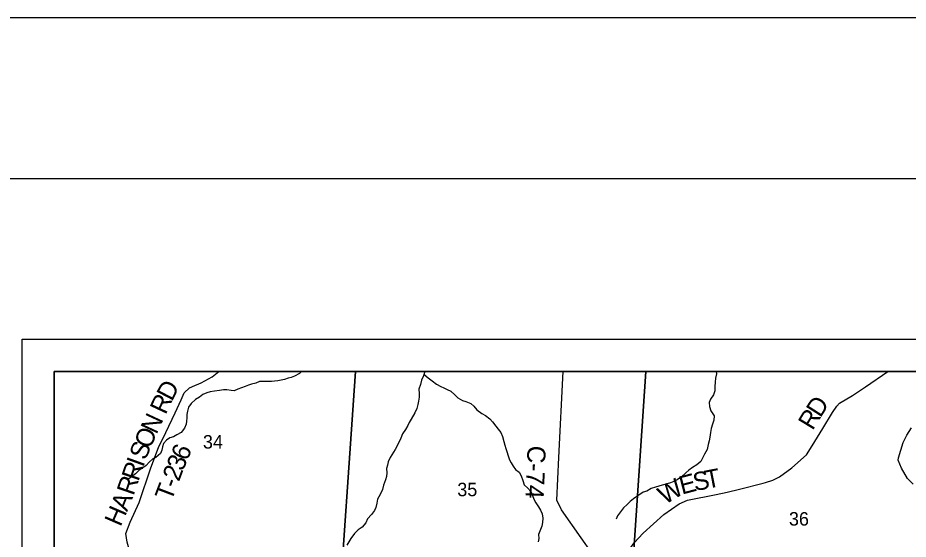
# Model space of a CAD drawing. Extents: x 0 to 34, y 0 to 22.
# Drawn here: x 23.403 to 26.174, y 20.378 to 22 of the extents above; entities that cross this region are included whole.
import ezdxf

# ---------------------------------------------------------------- set-up
doc = ezdxf.new("R2010")
doc.units = 0
for name, color, linetype in [('GM_X_City_Street', 7, 'Continuous'), ('GM_X_Corporation', 7, 'Continuous'), ('GM_X_County_Road', 7, 'Continuous'), ('GM_X_County_Road_Text', 7, 'Continuous'), ('GM_X_Minor_River', 7, 'Continuous'), ('GM_X_Section_Text', 7, 'Continuous'), ('GM_X_Township_Road', 7, 'Continuous'), ('GM_X_Township_Road_Text', 7, 'Continuous'), ('SH_Border', 7, 'Continuous'), ('SH_Cut_Line', 7, 'Continuous'), ('SH_Data', 7, 'Continuous')]:
    doc.layers.add(name, color=color, linetype=linetype)

msp = doc.modelspace()

# ---------------------------------------------------------------- linework, layer by layer
at = {"layer": 'GM_X_City_Street'}
msp.add_line((25.0865, 20.6324), (25.1003, 20.9), dxfattribs=at)
at = {"layer": 'GM_X_Corporation'}
for points in [[(24.4541, 20.9), (23.5167, 20.9), (23.5167, 20.1488), (24.2381, 20.0885), (24.3968, 20.0768)], [(26.3743, 20.9), (23.5167, 20.9), (23.5167, 20.1476), (23.8215, 20.1257), (24.2296, 20.084), (24.3889, 20.0736), (25.117, 20.0172), (25.2916, 20.0037), (25.482, 19.99), (25.7174, 19.9778), (26.3029, 19.931), (26.3351, 20.3683)], [(25.3573, 20.9), (24.4541, 20.9), (24.3968, 20.0768), (25.2979, 20.0049)], [(26.378, 20.9), (25.3573, 20.9), (25.2979, 20.0049), (26.302, 19.9328)]]:
    msp.add_lwpolyline(points, close=True, dxfattribs=at)
at = {"layer": 'GM_X_County_Road'}
for points in [[(25.2581, 20.2711), (25.3057, 20.3451), (25.3211, 20.367), (25.3495, 20.3964), (25.4138, 20.455), (25.4611, 20.4877), (25.4877, 20.4997), (25.5761, 20.5175), (25.6105, 20.5241), (25.6487, 20.5333), (25.723, 20.5524), (25.7304, 20.5544), (25.7524, 20.5617), (25.7731, 20.5722), (25.8117, 20.5997), (25.8576, 20.6409), (25.8752, 20.6681), (25.9079, 20.7222), (25.9386, 20.7725), (25.9523, 20.7916), (25.9606, 20.8013), (26.0006, 20.8252), (26.0414, 20.8523), (26.1102, 20.9)], [(25.2581, 20.2711), (25.2366, 20.286), (25.2278, 20.2932), (25.2057, 20.3136), (25.1884, 20.337), (25.1568, 20.3822), (25.0954, 20.4698), (25.0807, 20.4992), (25.0865, 20.6324)]]:
    msp.add_lwpolyline(points, dxfattribs=at)
at = {"layer": 'GM_X_Minor_River'}
for points in [[(24.2864, 20.9), (24.2801, 20.894), (24.2642, 20.885), (24.2539, 20.8809), (24.2441, 20.8794), (24.2334, 20.8749), (24.2225, 20.8727), (24.2126, 20.8709), (24.2024, 20.8702), (24.1925, 20.8691), (24.18, 20.8689), (24.1679, 20.8686), (24.1551, 20.869), (24.1441, 20.8638), (24.1304, 20.8601), (24.1209, 20.8575), (24.1103, 20.8534), (24.0997, 20.8485), (24.0883, 20.8444), (24.0766, 20.84), (24.0667, 20.8404), (24.0531, 20.8428), (24.0429, 20.8428), (24.0308, 20.8406), (24.0156, 20.8389), (24.0016, 20.8367), (23.9914, 20.8337), (23.9785, 20.8277), (23.9682, 20.8194), (23.956, 20.8123), (23.9423, 20.8007), (23.9343, 20.7886), (23.9312, 20.7765), (23.9292, 20.7662), (23.9292, 20.7552), (23.9283, 20.745), (23.9268, 20.7355), (23.9214, 20.7231), (23.9114, 20.7098), (23.8981, 20.7024), (23.8875, 20.6967), (23.8761, 20.693), (23.8662, 20.6859), (23.8567, 20.6753), (23.8536, 20.6651), (23.8513, 20.6553), (23.8467, 20.6451), (23.833, 20.6326), (23.8235, 20.6285), (23.8117, 20.6176), (23.8029, 20.6078), (23.7892, 20.5984), (23.7793, 20.5916), (23.769, 20.5819), (23.7572, 20.5717), (23.7443, 20.5623)], [(24.6695, 20.9), (24.6657, 20.8865), (24.6599, 20.8729), (24.6568, 20.8596), (24.651, 20.8452), (24.652, 20.8316), (24.6523, 20.8194), (24.65, 20.8077), (24.648, 20.7975), (24.6449, 20.7846), (24.6391, 20.771), (24.6276, 20.7513), (24.6215, 20.7415), (24.6169, 20.7313), (24.6093, 20.7189), (24.6008, 20.7056), (24.5947, 20.6928), (24.5878, 20.6773), (24.5774, 20.6569), (24.5621, 20.6327), (24.5556, 20.6191), (24.5536, 20.6081), (24.5509, 20.5979), (24.5516, 20.5842), (24.5508, 20.5729), (24.5477, 20.5626), (24.5415, 20.5464), (24.5376, 20.5331), (24.5303, 20.5169), (24.523, 20.5029), (24.5207, 20.49), (24.5172, 20.4767), (24.5133, 20.4669), (24.5038, 20.4552), (24.4916, 20.4417), (24.4862, 20.4288), (24.4748, 20.4152), (24.4626, 20.407), (24.4504, 20.3957), (24.4397, 20.3798), (24.4267, 20.3594)], [(25.5761, 20.9), (25.5776, 20.8926), (25.5749, 20.8786), (25.5733, 20.8669), (25.5728, 20.8528), (25.5727, 20.8396), (25.5681, 20.8271), (25.5585, 20.8135), (25.5551, 20.8036), (25.5561, 20.7904), (25.5602, 20.7774), (25.5699, 20.7618), (25.5691, 20.7486), (25.5648, 20.7357), (25.5609, 20.7225), (25.559, 20.7103), (25.557, 20.6956), (25.555, 20.6842), (25.5519, 20.6728), (25.548, 20.6569), (25.5403, 20.643), (25.5288, 20.6203), (25.5167, 20.609), (25.503, 20.6007), (25.4916, 20.5925), (25.4821, 20.5842), (25.4683, 20.5718), (25.4554, 20.5631), (25.4444, 20.5571), (25.4345, 20.553), (25.4243, 20.55), (25.408, 20.5464), (25.3981, 20.5434), (25.3879, 20.54), (25.3743, 20.536), (25.361, 20.5277), (25.3492, 20.5244), (25.3329, 20.5135), (25.3192, 20.5041), (25.3093, 20.4958), (25.299, 20.486), (25.2883, 20.4755), (25.2792, 20.4634), (25.2696, 20.4506), (25.265, 20.4403)], [(24.6672, 20.8919), (24.68, 20.8799), (24.6924, 20.8711), (24.7056, 20.86), (24.7192, 20.8528), (24.7293, 20.8493), (24.7391, 20.8439), (24.7512, 20.8381), (24.7633, 20.8274), (24.773, 20.8179), (24.7866, 20.8098), (24.7975, 20.8063), (24.8126, 20.8002), (24.8224, 20.7922), (24.8318, 20.7807), (24.8469, 20.7696), (24.8589, 20.7627), (24.8717, 20.7528), (24.88, 20.7429), (24.8905, 20.7295), (24.8976, 20.72), (24.9059, 20.7097), (24.9115, 20.6971), (24.9155, 20.6819), (24.9188, 20.6702), (24.9222, 20.6599), (24.9251, 20.6504), (24.9292, 20.6379), (24.9337, 20.6253), (24.9385, 20.6158), (24.9445, 20.6055), (24.9516, 20.5945), (24.9637, 20.5864), (24.97, 20.5754), (24.9745, 20.5606), (24.9789, 20.5473), (24.9906, 20.5366), (24.9992, 20.5267), (25.0052, 20.5141), (25.0089, 20.5031), (25.0149, 20.4913), (25.0231, 20.4783), (25.0298, 20.4681), (25.0351, 20.4574), (25.0372, 20.4434), (25.0364, 20.4305), (25.0337, 20.4191), (25.0302, 20.4081), (25.0237, 20.393), (25.0243, 20.3801), (25.0227, 20.3699)]]:
    msp.add_lwpolyline(points, dxfattribs=at)
at = {"layer": 'GM_X_Township_Road'}
for points in [[(23.9449, 20.8525), (23.9467, 20.8533), (23.974, 20.8648), (24.0075, 20.8832), (24.0283, 20.9)], [(23.7763, 20.2646), (23.7733, 20.2883), (23.757, 20.3219), (23.7436, 20.369), (23.7392, 20.3956), (23.753, 20.4312), (23.7809, 20.4925), (23.8167, 20.6004), (23.8405, 20.6629), (23.8638, 20.7102), (23.8929, 20.7707), (23.9117, 20.812), (23.9209, 20.8336), (23.9376, 20.8494), (23.9449, 20.8525)], [(26.1896, 20.5492), (26.1716, 20.5664), (26.1537, 20.5995), (26.1429, 20.6239), (26.1443, 20.6311), (26.1515, 20.6548), (26.1587, 20.6785), (26.1695, 20.7021), (26.1846, 20.7244)]]:
    msp.add_lwpolyline(points, dxfattribs=at)
at = {"layer": 'SH_Border'}
msp.add_lwpolyline([(1.5, 21.5), (33.5, 21.5), (33.5, 0.5), (1.5, 0.5)], close=True, dxfattribs=at)
at = {"layer": 'SH_Cut_Line'}
msp.add_lwpolyline([(0, 0), (34, 0), (34, 22), (0, 22)], close=True, dxfattribs=at)
at = {"layer": 'SH_Data'}
for points in [[(23.4167, 21), (30.4167, 21), (30.4167, 14), (23.4167, 14)], [(23.5167, 20.9), (30.3167, 20.9), (30.3167, 14.1), (23.5167, 14.1)]]:
    msp.add_lwpolyline(points, close=True, dxfattribs=at)

# ---------------------------------------------------------------- texts
at = {"layer": 'GM_X_County_Road_Text'}
for s, height, rotation, p in [('D', 0.0568, 57.4224, (25.9008, 20.7537)), ('R', 0.0568, 58.7149, (25.8767, 20.7141)), ('C-74', 0.05682, 267.5998, (24.9897, 20.67)), ('S', 0.0568, 11.1841, (25.5101, 20.5272)), ('T', 0.0568, 11.2139, (25.5477, 20.5346)), ('W', 0.0568, 30.8413, (25.4172, 20.4845)), ('E', 0.0568, 14.662, (25.4698, 20.5166))]:
    msp.add_text(s, height=height, rotation=rotation, dxfattribs=at).set_placement(p)
at = {"layer": 'GM_X_Section_Text'}
for s, p in [('34', (23.9792, 20.6601)), ('35', (24.7708, 20.5118)), ('36', (25.8029, 20.4205))]:
    msp.add_text(s, height=0.04186, rotation=0, dxfattribs=at).set_placement(p)
at = {"layer": 'GM_X_Township_Road_Text'}
for s, rotation, p in [('D', 62.4199, (23.8826, 20.8049)), ('R', 64.9536, (23.8631, 20.7632)), ('N', 65.03, (23.8346, 20.702)), ('O', 66.269, (23.8146, 20.6566)), ('S', 68.8039, (23.801, 20.6214)), ('6', 66.3765, (23.9295, 20.6193)), ('R', 71.3254, (23.7784, 20.5559)), ('I', 70.1456, (23.7932, 20.5998)), ('3', 67.9912, (23.9167, 20.5875)), ('2', 69.1931, (23.9045, 20.5553)), ('R', 71.0045, (23.7631, 20.5114)), ('-', 69.2468, (23.8963, 20.5337)), ('T', 69.2646, (23.8813, 20.494)), ('A', 68.0024, (23.7432, 20.462)), ('H', 66.6426, (23.7228, 20.4148))]:
    msp.add_text(s, height=0.0568, rotation=rotation, dxfattribs=at).set_placement(p)

doc.saveas('drawing.dxf')
